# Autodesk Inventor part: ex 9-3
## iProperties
Author: Administrator
Created: 2001-03
Part Number: ex 9-3
Document SubType Name: Modeling
Designer: Administrator
Control State: 0
Master: False
Checked Out: False
PropertySet Name: Design Tracking Control
Shininess: 100.0
PropertySet Name: _Private Model Information
Density: 0.0
Volumn: 0.0
Area: 0.0
PropertySet Name: Model Information
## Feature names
1. Extrusion1
